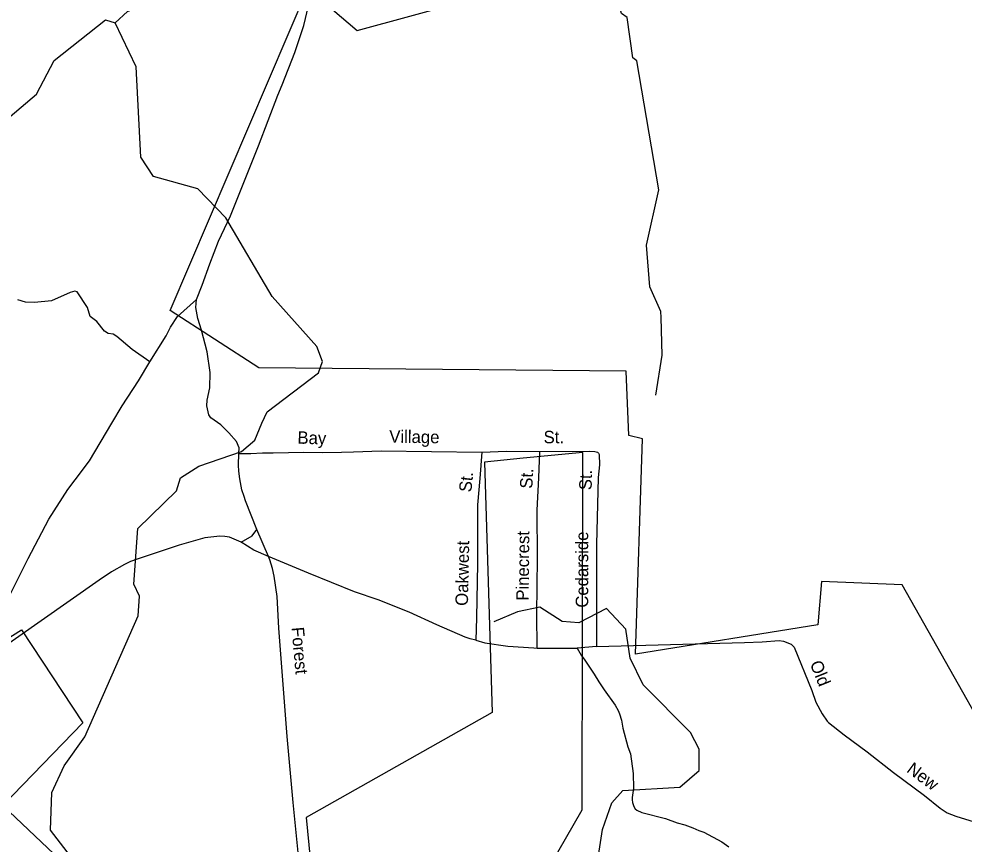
# Model space of a CAD drawing. Extents: x 2104537 to 2336408, y 34176 to 229611.
# Drawn here: x 2187530 to 2193201, y 89456 to 94408 of the extents above; entities that cross this region are included whole.
import ezdxf

# ---------------------------------------------------------------- set-up
doc = ezdxf.new("R2010")
doc.units = 0
for name, color, linetype in [('Exist Boundary Political City Limit New', 7, 'Continuous'), ('Exist Boundary Political City Limit New Hole', 7, 'Continuous'), ('Exist Hydrographic Creek Single Shore', 7, 'Continuous'), ('Exist Hydrographic Misc Water Feature', 7, 'Continuous'), ('Exist Road Non-System Type 51', 7, 'Continuous'), ('Exist Road Non-System Type 51 Label', 7, 'Continuous'), ('Map Preparation Boundary City Limit Buffer Line', 7, 'Continuous')]:
    doc.layers.add(name, color=color, linetype=linetype)

msp = doc.modelspace()

# ---------------------------------------------------------------- linework, layer by layer
at = {"layer": 'Exist Boundary Political City Limit New'}
for points in [[(2193626.5, 89599.2), (2192829.5, 91011.6), (2192345, 91032.5), (2192324.2, 90771.9), (2191230.2, 90594.7), (2191272, 91887.2), (2191188.5, 91908.1), (2191173, 92293.8), (2188969.8, 92314.6), (2188438.2, 92658.6), (2189264, 94592.2), (2189558.5, 94338.8), (2190552, 94609.6)], [(2186393.8, 90016.2), (2187545, 90740.6), (2187912.2, 90183), (2187433, 89687.8), (2187740.2, 89396)]]:
    msp.add_lwpolyline(points, dxfattribs=at)
at = {"layer": 'Exist Boundary Political City Limit New Hole'}
msp.add_lwpolyline([(2190323, 91748.1), (2190368.5, 90245.5), (2189254, 89614.9), (2189316.5, 88958.2), (2189317.2, 88916.2), (2189300.5, 88958.2), (2189307.5, 88488.1), (2189517.8, 87970.1), (2189728.2, 87597.8), (2189907.2, 87425.9), (2189907.5, 87441.2), (2189923.2, 87425.9), (2189933.8, 87962.7), (2190910.2, 89661.8), (2190913.8, 91806), (2190554.8, 91771.3), (2190323, 91748.1)], dxfattribs=at)
at = {"layer": 'Exist Hydrographic Creek Single Shore'}
for points in [[(2188106.5, 94384.1), (2188181.5, 94451.6), (2188505.5, 94596.2), (2188771.5, 94630.4), (2189213.6, 94582.5), (2189520.5, 94488)], [(2185006.5, 91625.8), (2185294.4, 92253.5), (2185433.4, 92595.3), (2185632.5, 92847.3), (2185906.5, 93055.3), (2186512.4, 93394.6), (2187476.6, 93822.2), (2187634.4, 93956.9), (2187741.5, 94158.3), (2188048.4, 94401.6), (2188106.5, 94384.1)]]:
    msp.add_lwpolyline(points, dxfattribs=at)
at = {"layer": 'Exist Hydrographic Misc Water Feature'}
for points in [[(2191351.6, 92149.5), (2191388.7, 92389.9), (2191383, 92616.4), (2191381.6, 92650.9), (2191314.5, 92799.8), (2191295.7, 93049.5), (2191368.6, 93382.8), (2191237.6, 94156.3), (2191212.6, 94173.1), (2191178.6, 94416.6), (2191144.5, 94440.2), (2191127.5, 94506.1), (2191018.6, 94639.5), (2190884.5, 94720.8), (2190725.6, 94737), (2190642.6, 94761.6)], [(2188498.5, 91653.6), (2188609.3, 91722.8), (2188866.2, 91812.2), (2188944.5, 91879.3), (2188986.6, 91982), (2189019.6, 92050.2), (2189326.5, 92283.8), (2189351.6, 92352.2), (2189317.5, 92441.4), (2189049.5, 92741.9), (2188771.5, 93213.1), (2188603.5, 93387), (2188336.5, 93461.1), (2188261.5, 93577.3), (2188233.4, 94119.2), (2188106.5, 94384.1)], [(2188705.6, 87453.3), (2188496.5, 87618.1), (2188445.6, 87760.2), (2188436.6, 87960.5), (2188076.5, 88243), (2188033.5, 88407.9), (2188148.5, 88707.5), (2188097.5, 88925), (2188004.6, 89166.3), (2187719.5, 89539.3), (2187726.5, 89765.5), (2187800.5, 89924.9), (2187924.6, 90099.6), (2188245.5, 90825.1), (2188252.5, 90943), (2188219.5, 91015.8), (2188242.4, 91350), (2188474.5, 91575.2), (2188498.5, 91653.6)], [(2189560.1, 88268.1), (2190047.5, 88323), (2190271.6, 88390.9), (2190536.5, 88576), (2190859.5, 88901.2), (2190958.5, 89076.4), (2191030.5, 89544.2), (2191087.5, 89703.9), (2191153.5, 89778), (2191494.6, 89797.7), (2191610.6, 89897.1), (2191610.6, 90025.1), (2191559.6, 90124.5), (2191274.5, 90412.1), (2191197.6, 90571.1), (2191171.6, 90745.5), (2191054.5, 90869.2), (2190888.6, 90783.8), (2190788.6, 90792.3), (2190654.7, 90876.9), (2190521.6, 90850), (2190379.5, 90790.3)]]:
    msp.add_lwpolyline(points, dxfattribs=at)
at = {"layer": 'Exist Road Non-System Type 51'}
for p, q in [((2189027.6, 91182.3), (2188956.9, 91344.1)), ((2189034.7, 91161.3), (2189027.6, 91182.3)), ((2190275, 90813.5), (2190272.1, 90679.2)), ((2190620.1, 90633.3), (2190638.7, 90632.1)), ((2190638.7, 90632.1), (2190878.8, 90631.1)), ((2190994.8, 90640.6), (2190878.8, 90631.1))]:
    msp.add_line(p, q, dxfattribs=at)
for points in [[(2188595.9, 92724.3), (2188629.3, 92810.4), (2188674.6, 92938.8), (2188727.8, 93072.9), (2188798.8, 93225.4), (2188966.4, 93646.3), (2189082.5, 93949.1), (2189110.1, 94011.1), (2189185.1, 94205.7), (2189240, 94368), (2189285, 94564.3), (2189331.7, 94734.4), (2189356.9, 94886.5), (2189400.9, 95226.9)], [(2188314.2, 92350.6), (2188209.8, 92424), (2188117.3, 92501.4), (2188095.2, 92515.2), (2188065.2, 92519), (2188043.1, 92533), (2187996.7, 92592.7), (2187956.6, 92622.5), (2187940.3, 92676.2), (2187879.7, 92770), (2187865.6, 92773.9), (2187837.6, 92765.6), (2187726, 92715), (2187624, 92706.3), (2187570.1, 92708), (2187523.9, 92721.7)], [(2188314.2, 92350.6), (2188413.2, 92505.2), (2188438.8, 92557.3), (2188480.5, 92621.5), (2188595.9, 92724.3)], [(2188849.4, 91799.8), (2188850.8, 91833.8), (2188835, 91871.7), (2188788.8, 91923.6), (2188740.5, 91971.1), (2188682.1, 92012.8), (2188670, 92030.7), (2188657.7, 92084.7), (2188659.5, 92118.7), (2188675.2, 92192.8), (2188676.6, 92286.7), (2188659.8, 92410.7), (2188625.7, 92539.1), (2188602.7, 92610.4), (2188592.1, 92676.2), (2188595.9, 92724.3)], [(2187247.7, 90501.8), (2187261.7, 90548.1), (2187307.6, 90610.2), (2187319.4, 90630.3), (2187343, 90692.5), (2187352.9, 90730.4), (2187362.5, 90751.9), (2187380.9, 90786.6), (2187420.8, 90850.5), (2187472.2, 90944.6), (2187585.4, 91169.5), (2187708.4, 91405.9), (2187823.8, 91584.1), (2187867.9, 91641.4), (2187953.8, 91756.5), (2188086.4, 91981.2), (2188149.8, 92085.5), (2188246.8, 92236.3), (2188314.2, 92350.6)], [(2188881.8, 91540.8), (2188867.9, 91582.4), (2188855.3, 91647.5), (2188848.4, 91693.5), (2188846.6, 91730), (2188849.4, 91799.8)], [(2188849.4, 91799.8), (2188921.4, 91800.4), (2188991.5, 91804.6), (2189055.4, 91803.2), (2189239.4, 91808.2), (2189353.3, 91804.8), (2189465.4, 91807.6), (2189538.1, 91810.5), (2189704.2, 91816.2), (2190306.4, 91808.1)], [(2190306.4, 91808.1), (2190296, 91649.1), (2190280.7, 91491.4), (2190282, 91139.3), (2190275, 90813.5)], [(2190306.4, 91808.1), (2190454.5, 91813.5), (2190654.6, 91811.2)], [(2190638.7, 90632.1), (2190638, 90835.8), (2190641.6, 91172.1), (2190639.9, 91459.8), (2190649.7, 91654.6), (2190654.6, 91811.2)], [(2190654.6, 91811.2), (2190953.2, 91813), (2190984.3, 91812.4), (2191000.6, 91808.5), (2191007.4, 91801.5), (2191010.8, 91792.9), (2191013.2, 91730.8), (2191005.3, 91656.5), (2190994.5, 91254.5), (2190994.8, 90640.6)], [(2188956.9, 91344.1), (2188890, 91516), (2188881.8, 91540.8)], [(2188863.2, 91267.8), (2188928.9, 91305.9), (2188956.9, 91344.1)], [(2188863.2, 91267.8), (2188793, 91297.4), (2188765.1, 91301.5), (2188734.4, 91304.1), (2188645.9, 91293), (2188491.2, 91250.4), (2188239.9, 91166), (2188199.6, 91151.4), (2188176, 91140.5)], [(2189027.6, 91182.3), (2188939.1, 91220.1), (2188863.2, 91267.8)], [(2188176, 91140.5), (2188162.5, 91134.4), (2188085.9, 91089.2), (2188012, 91038.8), (2187333.6, 90566.4), (2187247.7, 90501.8)], [(2190272.1, 90679.2), (2190237.8, 90686.8), (2190207.9, 90698.2), (2190036.7, 90772.3), (2189871.5, 90848), (2189686, 90921), (2189543.2, 90970.2), (2189267.8, 91081.2), (2189027.6, 91182.3)], [(2189349.1, 88247), (2189335.9, 88290.8), (2189323.9, 88350.8), (2189280.7, 88644.9), (2189174.9, 89704.4), (2189139.6, 90100.4), (2189088.8, 90750.6), (2189078.4, 90942.4), (2189062, 91063.2), (2189051.8, 91110.3), (2189034.7, 91161.3)], [(2190272.1, 90679.2), (2190324.3, 90663.8), (2190462.4, 90643.7), (2190620.1, 90633.3)], [(2190878.8, 90631.1), (2190903.6, 90589.2), (2190926, 90559.6), (2190980.8, 90476.2), (2191009.6, 90430)], [(2190994.8, 90640.6), (2191882.7, 90665.8), (2191988.4, 90669.3), (2192090.6, 90676.5), (2192116.5, 90673.1), (2192163, 90655.8), (2192181.1, 90637.7), (2192286.6, 90377.1), (2192311.5, 90307.4), (2192349.8, 90237.5), (2192378.9, 90194.3), (2192388.2, 90185.2), (2192481.9, 90111.9), (2192619.4, 90009.5), (2192777.1, 89885.4), (2192963.1, 89747.9), (2193058, 89671), (2193100.2, 89643.6), (2193150.6, 89622.3), (2193345.6, 89562.7), (2193405.7, 89549.4)], [(2191009.6, 90430), (2191040.3, 90380.9), (2191107.1, 90290), (2191125.8, 90256.9), (2191134, 90238.3), (2191145.7, 90198.4), (2191153.3, 90150.7), (2191182.6, 90038.9), (2191199.2, 89997.3), (2191214.6, 89879.2), (2191217.9, 89791.5), (2191208.9, 89736.2), (2191209, 89721.1), (2191211.3, 89705), (2191219.4, 89681.2), (2191228, 89667.6), (2191237.6, 89659.6), (2191267.9, 89645.9), (2191408.3, 89609.7), (2191479.9, 89583.7), (2191525, 89571.3), (2191572.9, 89554), (2191609.9, 89536.9), (2191639.6, 89526.8), (2191746.4, 89468.3), (2191788.5, 89438.6)]]:
    msp.add_lwpolyline(points, dxfattribs=at)
at = {"layer": 'Map Preparation Boundary City Limit Buffer Line'}
for points in [[(2193626.5, 89599.2), (2192829.5, 91011.6), (2192345, 91032.5), (2192324.2, 90771.9), (2191230.2, 90594.7), (2191272, 91887.2), (2191188.5, 91908.1), (2191173, 92293.8), (2188969.8, 92314.6), (2188438.2, 92658.6), (2189264, 94592.2), (2189558.5, 94338.8), (2190552, 94609.6)], [(2190323, 91748.1), (2190368.5, 90245.5), (2189254, 89614.9), (2189316.5, 88958.2), (2189317.2, 88916.2), (2189300.5, 88958.2), (2189307.5, 88488.1), (2189517.8, 87970.1), (2189728.2, 87597.8), (2189907.2, 87425.9), (2189907.5, 87441.2), (2189923.2, 87425.9), (2189933.8, 87962.7), (2190910.2, 89661.8), (2190913.8, 91806), (2190554.8, 91771.3), (2190323, 91748.1)], [(2186393.8, 90016.2), (2187545, 90740.6), (2187912.2, 90183), (2187433, 89687.8), (2187740.2, 89396)]]:
    msp.add_lwpolyline(points, dxfattribs=at)

# ---------------------------------------------------------------- texts
at = {"layer": 'Exist Road Non-System Type 51 Label'}
for s, rotation, p in [('Bay', 358.2865, (2189200, 91858.6)), ('Village', 359.2359, (2189751.5, 91864.7)), ('St.', 0.3406, (2190678, 91860.6)), ('St.', 84.4653, (2190244.3, 91565.1)), ('St.', 87.1142, (2190610, 91586.9)), ('St.', 88.4582, (2190965.9, 91578.7)), ('Pinecrest', 89.3951, (2190588.2, 90915.9)), ('Cedarside', 90.0254, (2190945.5, 90874.2)), ('Oakwest', 88.7699, (2190223.5, 90884.8)), ('Forest', 275.0968, (2189165, 90755.3)), ('Old', 292.047, (2192274, 90539.4)), ('New', 323.5349, (2192851, 89892))]:
    msp.add_text(s, height=75, rotation=rotation, dxfattribs=at).set_placement(p)

doc.saveas('drawing.dxf')
